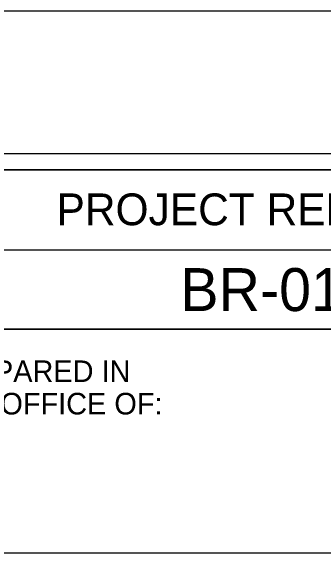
# Model space of a CAD drawing. Extents: x 1298931 to 1298964.7, y 1260171.5 to 1260193.5.
# Drawn here: x 1298960.631 to 1298961.616, y 1260191.741 to 1260193.475 of the extents above; entities that cross this region are included whole.
import ezdxf

# ---------------------------------------------------------------- set-up
doc = ezdxf.new("R2010")
doc.units = 0
for name, color, linetype in [('Default', 7, 'Continuous'), ('Sheet Cutting Line CELL', 7, 'Continuous'), ('Sheet Data Field CELL', 7, 'Continuous'), ('Sheet Plot Border Inside CELL', 7, 'Continuous'), ('Sheet Plot Border Outside CELL', 7, 'Continuous'), ('Sheet Sticker Exception Certification CELL', 7, 'Continuous'), ('Sheet Summary Combination CELL', 7, 'Continuous'), ('Sheet Typical CELL', 7, 'Continuous')]:
    doc.layers.add(name, color=color, linetype=linetype)

msp = doc.modelspace()

# ---------------------------------------------------------------- linework, layer by layer
at = {"layer": 'Sheet Cutting Line CELL'}
msp.add_line((1298964.6711, 1260193.4748), (1298930.9911, 1260193.4748), dxfattribs=at)
at = {"layer": 'Sheet Plot Border Inside CELL'}
msp.add_lwpolyline([(1298964.5811, 1260193.0258), (1298931.2511, 1260193.0258), (1298931.2511, 1260171.9238), (1298964.5811, 1260171.9238)], close=True, dxfattribs=at)
at = {"layer": 'Sheet Plot Border Outside CELL'}
msp.add_lwpolyline([(1298964.6711, 1260193.4748), (1298930.9911, 1260193.4748), (1298930.9911, 1260171.4748), (1298964.6711, 1260171.4748)], close=True, dxfattribs=at)
at = {"layer": 'Sheet Sticker Exception Certification CELL'}
msp.add_line((1298960.3301, 1260191.7702), (1298964.3308, 1260191.7702), dxfattribs=at)
at = {"layer": 'Sheet Summary Combination CELL'}
for p, q in [((1298960.3301, 1260192.7238), (1298964.3311, 1260192.7238)), ((1298960.3301, 1260192.4738), (1298964.3311, 1260192.4738))]:
    msp.add_line(p, q, dxfattribs=at)
for points in [[(1298964.3311, 1260192.9748), (1298934.3311, 1260192.9748), (1298934.3311, 1260171.9748), (1298964.3311, 1260171.9748)], [(1298960.3301, 1260192.9748), (1298964.3311, 1260192.9748), (1298964.3311, 1260192.4738), (1298960.3301, 1260192.4738)]]:
    msp.add_lwpolyline(points, close=True, dxfattribs=at)
at = {"layer": 'Sheet Typical CELL'}
msp.add_lwpolyline([(1298964.3308, 1260192.4738), (1298960.3301, 1260192.4738), (1298960.3301, 1260191.7702), (1298964.3308, 1260191.7702)], close=True, dxfattribs=at)

# ---------------------------------------------------------------- texts
at = {"layer": 'Default'}
for s, p in [('PREPARED IN ', (1298960.3903, 1260192.3074)), ('THE OFFICE OF:', (1298960.3903, 1260192.2054))]:
    msp.add_text(s, height=0.068, rotation=360, dxfattribs=at).set_placement(p)
at = {"layer": 'Sheet Data Field CELL'}
msp.add_text('BR-0120', height=0.135, dxfattribs=at).set_placement((1298961.1638, 1260192.5308))
at = {"layer": 'Sheet Summary Combination CELL'}
msp.add_text('PROJECT REFERENCE NO.', height=0.100002, dxfattribs=at).set_placement((1298960.7741, 1260192.8008))

doc.saveas('drawing.dxf')
